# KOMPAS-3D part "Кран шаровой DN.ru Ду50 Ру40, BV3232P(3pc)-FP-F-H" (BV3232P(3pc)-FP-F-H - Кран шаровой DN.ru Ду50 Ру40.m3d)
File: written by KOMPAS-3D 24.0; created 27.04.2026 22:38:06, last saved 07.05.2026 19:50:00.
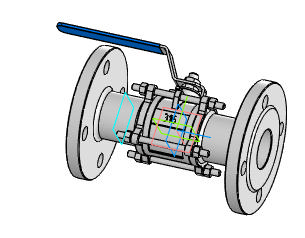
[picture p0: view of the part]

Document properties: Автор: Максим; Полное имя файла: BVxxP(3pc)-FP-F-H - Кран шаровой DN.ru Ду50 Ру40.cdw

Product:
- Body: Тело 1  | qty 1
    Масса: 8.142065
- Part/product: Кран шаровой DN.ru Ду50 Ру40  | designation BV3232P(3pc)-FP-F-H
    Масса: 8.07
    Раздел спецификации: Прочие изделия
    Форматы листов документа: A2
    Примечание: D160-22806

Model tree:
1. Операция без истории:1
2. Эскиз:1  (with: Ребро.Операция без истории:1)
3. Элемент выдавливания:1
     Расстояние 1 = 10
4. Эскиз:2  (with: Грань.Операция без истории:1)
5. Элемент выдавливания:2
     Расстояние 1 = 10; Расстояние 2 = 30
6. Эскиз:3  (with: Грань.Элемент выдавливания:2)
7. Элемент выдавливания:3  (with: Грань.Операция без истории:1)
     Расстояние 1 = 30
8. Эскиз:4  (with: Грань.Операция без истории:1)
9. Элемент выдавливания:4
     Расстояние 1 = 8
10. Фаска:1  (with: Ребро.Элемент выдавливания:4)
     Угол = 45; Длина 1 = 1.6; Длина 2 = 1.6
11. Скругление:1  (with: Ребро.Элемент выдавливания:1)
     Радиус = 3
12. Скругление:2  (with: Ребро.Элемент выдавливания:1)
     Радиус = 6
13. Эскиз:5  (with: Ребро.Элемент выдавливания:1, Ребро.Элемент выдавливания:3)
14. Элемент выдавливания:5
     Расстояние 1 = 23
15. Эскиз:6  (with: Ребро.Элемент выдавливания:5)
16. Элемент выдавливания:6
     Расстояние 1 = 24
17. Скругление:3  (with: Ребро.Элемент выдавливания:6)
     Радиус = 7.5
18. Скругление:4  (with: Ребро.Элемент выдавливания:6)
     Радиус = 0.5
19. Смещенная плоскость:1
     Расстояние = -69
20. Эскиз:7  (with: Ребро.Операция без истории:1)
21. Элемент выдавливания:7
     Расстояние 1 = 26
22. Зеркальный массив:1
23. Экземпляр ( 1 )
24. Экземпляр ( 2 )  (with: Элемент выдавливания:7)
25. Эскиз:8  (with: Грань.Операция без истории:1)
26. Элемент выдавливания:8
     Расстояние 1 = 10
27. Эскиз:9  (with: Грань.Операция без истории:1)
28. Элемент выдавливания:9
     Расстояние 1 = 0.2
29. Скругление:5  (with: Ребро.Элемент выдавливания:1)
     Радиус = 3
30. Скругление:6  (with: Ребро.Элемент выдавливания:1)
     Радиус = 6
31. Фаска:2  (with: Ребро.Элемент выдавливания:5)
     Угол = 45; Длина 1 = 5; Длина 2 = 5
32. Эскиз:10  (with: Грань.Операция без истории:1, Ребро.Операция без истории:1)
33. Элемент выдавливания:10  (with: Грань.Операция без истории:1)
     Расстояние 2 = 230
34. Эскиз:11  (with: Грань.Операция без истории:1)
35. Элемент выдавливания:11
     Расстояние 1 = 0.2
36. Эскиз:12  (with: Грань.Элемент выдавливания:6, Ребро.Скругление:4, Ребро.Элемент выдавливания:6)
37. Элемент выдавливания:12
     Расстояние 2 = 0.2

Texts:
  Точка начала. Х
  Точка начала. Y
  Точка начала. Z
  BV3232P(3pc)-FP-F-H
  DN50 PN40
